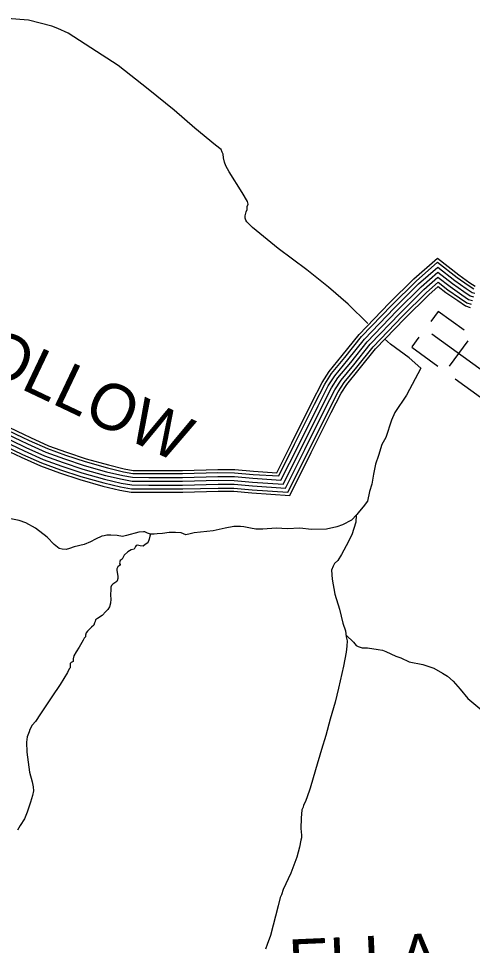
# Model space of a CAD drawing. Extents: x 1551132 to 1791609, y 378168 to 563823.
# Drawn here: x 1665834 to 1669476, y 396855 to 404298 of the extents above; entities that cross this region are included whole.
import ezdxf

# ---------------------------------------------------------------- set-up
doc = ezdxf.new("R2010")
doc.units = 0
for name, color, linetype in [('DESIGN - ROW - Right-of-Way and Easement Labels', 7, 'Continuous'), ('DESIGN - TRANSPORTATION - Text', 7, 'Continuous'), ('DESIGN - UTILITIES - Cable (Underground) with Text', 7, 'Continuous'), ('SURVEY - PROPERTY - Owners', 7, 'Continuous'), ('SURVEY - TRANSPORTATION - Roads', 7, 'Continuous')]:
    doc.layers.add(name, color=color, linetype=linetype)

msp = doc.modelspace()

# ---------------------------------------------------------------- linework, layer by layer
at = {"layer": 'DESIGN - TRANSPORTATION - Text'}
for points in [[(1668636.694, 401848.028), (1668479.889, 402002.974), (1668320.46, 402141.836), (1668147.03, 402278.747), (1667917.744, 402449.943), (1667712.441, 402619.031), (1667678.575, 402651.215), (1667666.633, 402665.282), (1667658.684, 402679.333), (1667652.75, 402695.383), (1667652.817, 402713.4), (1667660.942, 402745.401), (1667669.008, 402763.385), (1667669.1, 402787.411), (1667677.175, 402807.403), (1667671.267, 402829.453), (1667627.543, 402899.722), (1667524.212, 403066.368), (1667498.404, 403114.527), (1667486.53, 403144.62), (1667478.663, 403178.687), (1667474.78, 403208.738), (1667468.838, 403224.789), (1667458.922, 403244.856), (1667415.073, 403281.082), (1667249.635, 403417.96), (1667082.239, 403562.864), (1666874.927, 403729.96), (1666633.717, 403919.223), (1666414.322, 404062.344), (1666232.809, 404179.272), (1666148.978, 404217.681), (1666101.063, 404235.915), (1665915.292, 404284.782), (1665743.379, 404297.549)], [(1669061.125, 401490.285), (1668968.111, 401572.354), (1668818.573, 401683.132), (1668770.99, 401725.491)], [(1669061.125, 401490.285), (1668945.828, 401274.738), (1668853.305, 401134.984), (1668825.072, 401073.033), (1668780.54, 400933.071), (1668748.332, 400877.152), (1668721.999, 400789.167), (1668697.733, 400719.19), (1668681.425, 400639.171), (1668667.117, 400559.144), (1668650.893, 400499.142), (1668632.601, 400423.14), (1668598.427, 400377.239), (1668570.294, 400341.322), (1668548.203, 400315.388), (1668504.038, 400269.528), (1668431.906, 400231.802), (1668387.857, 400215.976), (1668305.801, 400198.309), (1668183.82, 400194.842), (1668089.881, 400205.268), (1667991.883, 400199.684), (1667901.927, 400206.084), (1667793.921, 400198.551), (1667737.922, 400196.792), (1667693.965, 400204.993), (1667642.016, 400215.234), (1667614.042, 400219.36), (1667588.051, 400219.476), (1667562.051, 400219.584), (1667492.02, 400205.876), (1667395.955, 400184.275), (1667243.925, 400168.925), (1667209.901, 400159.058), (1667175.885, 400153.199), (1667157.919, 400161.291), (1667139.944, 400167.375), (1667093.971, 400171.583), (1667041.98, 400169.808), (1666987.956, 400162.033), (1666945.966, 400160.216), (1666921.958, 400158.316), (1666907.967, 400158.383), (1666891.967, 400158.449), (1666870.001, 400166.558), (1666846.051, 400176.666), (1666836.052, 400176.716), (1666800.044, 400172.866), (1666699.963, 400147.274), (1666667.947, 400139.407), (1666625.981, 400147.599), (1666574.008, 400149.832), (1666542.017, 400149.965), (1666519.992, 400144.057), (1666501.984, 400140.132), (1666451.911, 400118.323), (1666411.836, 400096.481), (1666361.763, 400074.672), (1666281.706, 400054.996), (1666243.657, 400041.146), (1666215.641, 400035.262), (1666183.658, 400037.404), (1666159.684, 400043.521), (1666119.81, 400073.73), (1666064.061, 400134.04), (1665970.355, 400204.533), (1665892.54, 400248.918), (1665838.625, 400267.177), (1665772.685, 400279.477)], [(1668542.562, 400309.529), (1668539.095, 400252.728), (1668506.712, 400150.758), (1668462.38, 400062.847), (1668424.123, 399992.937), (1668395.948, 399947.011), (1668369.857, 399921.094), (1668357.783, 399901.127), (1668345.658, 399869.142), (1668349.374, 399797.04), (1668372.899, 399674.804), (1668408.423, 399554.509), (1668435.989, 399442.256), (1668457.747, 399382.096), (1668463.563, 399334.02), (1668469.43, 399299.952), (1668467.263, 399257.91), (1668463.08, 399209.875), (1668440.655, 399097.847), (1668399.973, 398919.826), (1668373.548, 398807.814), (1668333.024, 398671.836), (1668298.525, 398539.832), (1668264.101, 398427.863), (1668215.477, 398263.883), (1668172.919, 398117.904), (1668146.62, 398039.936), (1668134.495, 398005.943), (1668120.404, 397981.984), (1668118.345, 397965.967), (1668106.262, 397944), (1668102.004, 397877.94), (1668097.679, 397793.862), (1668103.479, 397741.778), (1668103.396, 397719.761), (1668099.321, 397699.752), (1668087.104, 397643.742), (1668066.796, 397563.74), (1668018.314, 397435.803), (1667957.816, 397303.924), (1667943.658, 397261.932), (1667933.574, 397239.956), (1667917.316, 397171.946), (1667856.409, 396933.94), (1667828.135, 396861.988), (1667815.994, 396823.995)], [(1666892.825, 400158.449), (1666887.042, 400141.824), (1666882.95, 400117.815), (1666870.834, 400087.839), (1666850.785, 400073.905), (1666832.743, 400061.972), (1666808.76, 400064.08), (1666788.786, 400070.172), (1666778.77, 400066.213), (1666772.745, 400058.23), (1666760.67, 400038.263), (1666736.645, 400030.354), (1666710.588, 400014.454), (1666680.497, 399988.553), (1666664.372, 399956.585), (1666648.339, 399946.652), (1666644.264, 399926.643), (1666650.447, 399914.843), (1666644.181, 399906.617), (1666630.14, 399894.667), (1666624.081, 399878.675), (1666622.031, 399864.666), (1666629.856, 399820.582), (1666629.79, 399802.565), (1666626.106, 399783.364), (1666621.69, 399776.572), (1666589.607, 399754.688), (1666579.574, 399744.721), (1666575.516, 399730.721), (1666573.457, 399714.712), (1666571.274, 399666.669), (1666575.149, 399634.61), (1666573.032, 399604.593), (1666564.916, 399574.592), (1666550.833, 399552.625), (1666534.775, 399536.683), (1666504.659, 399504.773), (1666466.577, 399480.914), (1666452.535, 399468.964), (1666448.485, 399456.964), (1666444.444, 399444.972), (1666438.377, 399426.98), (1666418.319, 399411.046), (1666400.253, 399393.104), (1666386.203, 399379.153), (1666376.154, 399365.178), (1666372.079, 399347.178), (1666372.029, 399333.161), (1666361.979, 399321.194), (1666353.921, 399305.21), (1666321.721, 399251.283), (1666297.572, 399211.349), (1666277.456, 399179.398), (1666273.373, 399157.389), (1666271.323, 399145.389), (1666271.281, 399135.372), (1666257.256, 399127.43), (1666249.231, 399119.455), (1666249.165, 399103.438), (1666247.131, 399095.438), (1666249.09, 399083.412), (1666241.057, 399075.437), (1666226.957, 399047.47), (1666168.6, 398951.617), (1666100.226, 398851.798), (1666011.72, 398716.036), (1665971.488, 398654.142), (1665943.38, 398624.225), (1665925.255, 398590.266), (1665919.172, 398570.273), (1665903.023, 398530.297), (1665896.864, 398488.28), (1665900.556, 398408.169), (1665921.922, 398245.89), (1665943.621, 398169.713), (1665951.455, 398127.628), (1665953.329, 398095.586), (1665945.196, 398059.577), (1665928.988, 398005.584), (1665904.689, 397925.606), (1665882.481, 397871.638), (1665848.282, 397817.729), (1665826.149, 397781.786)], [(1668461.98, 399347.087), (1668521.378, 399289.71), (1668543.27, 399263.585), (1668559.236, 399255.51), (1668591.185, 399245.359), (1668633.176, 399245.176), (1668719.107, 399230.784), (1668753.081, 399226.626), (1668781.031, 399216.492), (1668860.87, 399178.099), (1668900.803, 399163.916), (1668968.668, 399133.582), (1669078.557, 399111.073), (1669166.43, 399082.655), (1669236.262, 399042.304), (1669274.152, 399016.112), (1669321.984, 398975.853), (1669377.716, 398911.543), (1669439.415, 398837.182), (1669551.037, 398744.597)]]:
    msp.add_lwpolyline(points, dxfattribs=at)
at = {"layer": 'DESIGN - UTILITIES - Cable (Underground) with Text'}
for p, q in [((1669200.74, 401945.692), (1669142.092, 401864.993)), ((1669408.379, 401794.773), (1669200.656, 401945.601)), ((1669046.57, 401740.345), (1668988.497, 401660.263)), ((1669439.304, 401710.517), (1669289.934, 401505.436)), ((1668988.097, 401659.738), (1669199.028, 401506.493)), ((1669337.41, 401405.913), (1669540.907, 401258.21))]:
    msp.add_line(p, q, dxfattribs=at)
msp.add_lwpolyline([(1669148.868, 401766.395), (1669604.304, 401435.657)], dxfattribs=at)
at = {"layer": 'SURVEY - PROPERTY - Owners'}
msp.add_lwpolyline([(1665665.421, 400962.003), (1665892.599, 400854.134), (1666042.095, 400786.907), (1666191.684, 400733.689), (1666351.272, 400680.404), (1666532.867, 400628.953), (1666664.614, 400597.902), (1666746.496, 400583.26), (1666878.459, 400582.252), (1667150.403, 400582.169), (1667434.396, 400590.011), (1667564.36, 400589.011), (1667712.231, 400575.869), (1667958.067, 400559.969), (1668104.106, 400851.218), (1668264.36, 401174.402), (1668345.467, 401331.973), (1668396.016, 401411.691), (1668498.888, 401537.061), (1668632.035, 401702.249), (1668869.747, 401950.747), (1669065.067, 402143.494), (1669197.872, 402260.631), (1669315.203, 402169.62), (1669406.726, 402104.835), (1669458.466, 402070.393), (1669484.774, 402061.867)], dxfattribs=at)
at = {"layer": 'SURVEY - TRANSPORTATION - Roads'}
for points in [[(1665704.762, 401039.322), (1665928.982, 400932.852), (1666074.461, 400867.434), (1666219.95, 400815.675), (1666376.838, 400763.29), (1666554.642, 400712.914), (1666682.205, 400682.855), (1666754.512, 400669.921), (1666878.801, 400668.971), (1667149.22, 400668.888), (1667433.53, 400676.738), (1667568.535, 400675.697), (1667718.865, 400662.338), (1667906.31, 400650.213), (1668026.507, 400889.919), (1668186.962, 401213.511), (1668270.152, 401375.124), (1668325.617, 401462.609), (1668431.615, 401591.779), (1668566.829, 401759.534), (1668807.948, 402011.599), (1669005.885, 402206.929), (1669194.323, 402373.134), (1669366.852, 402239.305), (1669455.808, 402176.337), (1669496.565, 402149.203)], [(1665679.487, 400989.645), (1665905.607, 400882.276), (1666053.662, 400815.691), (1666201.792, 400762.998), (1666360.413, 400710.038), (1666540.65, 400658.971), (1666670.906, 400628.27), (1666749.362, 400614.236), (1666878.584, 400613.253), (1667149.978, 400613.17), (1667434.088, 400621.012), (1667565.851, 400620.003), (1667714.606, 400606.778), (1667939.568, 400592.228), (1668076.365, 400865.052), (1668236.694, 401188.385), (1668318.543, 401347.398), (1668370.85, 401429.892), (1668474.839, 401556.62), (1668608.728, 401722.725), (1668847.655, 401972.498), (1669043.909, 402166.17), (1669196.606, 402300.849), (1669333.669, 402194.529), (1669424.275, 402130.394), (1669472.083, 402098.568), (1669494.332, 402091.36)], [(1665693.545, 401017.28), (1665918.607, 400910.419), (1666065.237, 400844.484), (1666211.891, 400792.307), (1666369.546, 400739.664), (1666548.434, 400688.988), (1666677.189, 400658.637), (1666752.229, 400645.22), (1666878.709, 400644.254), (1667149.553, 400644.17), (1667433.78, 400652.021), (1667567.351, 400650.988), (1667716.973, 400637.696), (1667921.068, 400624.495), (1668048.624, 400878.885), (1668209.02, 401202.361), (1668291.618, 401362.823), (1668345.684, 401448.092), (1668450.79, 401576.179), (1668585.42, 401743.209), (1668825.564, 401994.249), (1669022.76, 402188.845), (1669195.339, 402341.066), (1669352.127, 402219.446), (1669441.817, 402155.953), (1669485.707, 402126.744)], [(1665651.355, 400934.361), (1665879.591, 400825.991), (1666030.529, 400758.123), (1666181.575, 400704.38), (1666342.13, 400650.77), (1666525.084, 400598.936), (1666658.323, 400567.535), (1666743.629, 400552.285), (1666878.334, 400551.251), (1667150.828, 400551.168), (1667434.704, 400559.01), (1667562.868, 400558.018), (1667709.856, 400544.96), (1667976.567, 400527.71), (1668131.847, 400837.384), (1668292.026, 401160.418), (1668372.391, 401316.547), (1668421.182, 401393.491), (1668522.938, 401517.503), (1668655.343, 401681.774), (1668891.838, 401928.997), (1669086.225, 402120.819), (1669199.139, 402220.413), (1669296.737, 402144.711), (1669389.176, 402079.276), (1669444.85, 402042.217), (1669475.216, 402032.375)], [(1665665.421, 400962.003), (1665892.599, 400854.134), (1666042.095, 400786.907), (1666191.684, 400733.689), (1666351.272, 400680.404), (1666532.867, 400628.953), (1666664.614, 400597.902), (1666746.496, 400583.26), (1666878.459, 400582.252), (1667150.403, 400582.169), (1667434.396, 400590.011), (1667564.36, 400589.011), (1667712.231, 400575.869), (1667958.067, 400559.969), (1668104.106, 400851.218), (1668264.36, 401174.402), (1668345.467, 401331.973), (1668396.016, 401411.691), (1668498.888, 401537.061), (1668632.035, 401702.249), (1668869.747, 401950.747), (1669065.067, 402143.494), (1669197.872, 402260.631), (1669315.203, 402169.62), (1669406.726, 402104.835), (1669458.466, 402070.393), (1669484.774, 402061.867)], [(1665665.421, 400962.003), (1665892.599, 400854.134), (1666042.095, 400786.907), (1666191.684, 400733.689), (1666351.272, 400680.404), (1666532.867, 400628.953), (1666664.614, 400597.902), (1666746.496, 400583.26), (1666878.459, 400582.252), (1667150.403, 400582.169), (1667434.396, 400590.011), (1667564.36, 400589.011), (1667712.231, 400575.869), (1667958.067, 400559.969), (1668104.106, 400851.218), (1668264.36, 401174.402), (1668345.467, 401331.973), (1668396.016, 401411.691), (1668498.888, 401537.061), (1668632.035, 401702.249), (1668869.747, 401950.747), (1669065.067, 402143.494), (1669197.872, 402260.631), (1669315.203, 402169.62), (1669406.726, 402104.835), (1669458.466, 402070.393), (1669484.774, 402061.867)], [(1665625.63, 400883.793), (1665855.8, 400774.507), (1666009.355, 400705.447), (1666163.093, 400650.753), (1666325.414, 400596.56), (1666510.843, 400544.026), (1666646.823, 400511.975), (1666738.379, 400495.6), (1666878.109, 400494.533), (1667151.603, 400494.45), (1667435.271, 400502.284), (1667560.135, 400501.325), (1667705.515, 400488.4), (1668010.416, 400468.683), (1668182.604, 400812.075), (1668342.65, 401134.842), (1668421.657, 401288.321), (1668467.222, 401360.19), (1668566.937, 401481.71), (1668697.992, 401644.298), (1668932.253, 401889.196), (1669124.932, 402079.334), (1669201.464, 402146.836), (1669262.962, 402099.135), (1669357.077, 402032.508), (1669419.925, 401990.674), (1669457.733, 401978.424)], [(1665637.297, 400906.727), (1665866.591, 400797.849), (1666018.954, 400729.33), (1666171.476, 400675.071), (1666332.997, 400621.144), (1666517.301, 400568.918), (1666652.039, 400537.167), (1666740.762, 400521.3), (1666878.209, 400520.25), (1667151.253, 400520.167), (1667435.013, 400528.001), (1667561.368, 400527.034), (1667707.49, 400514.042), (1667995.066, 400495.442), (1668159.588, 400823.551), (1668319.701, 401146.443), (1668399.316, 401301.122), (1668446.348, 401375.29), (1668546.987, 401497.944), (1668678.651, 401661.29), (1668913.929, 401907.246), (1669107.374, 402098.143), (1669200.406, 402180.195), (1669278.279, 402119.794), (1669371.635, 402053.717), (1669431.225, 402014.041), (1669465.666, 402002.882)]]:
    msp.add_lwpolyline(points, dxfattribs=at)

# ---------------------------------------------------------------- texts
at = {"layer": 'DESIGN - ROW - Right-of-Way and Easement Labels'}
for s, height, rotation, p in [('HOLLOW', 369.9946, 334.6002806, (1665171.908, 401647.679)), ('ELLA', 369.9914, 2.57865, (1668009.089, 396531.987))]:
    msp.add_text(s, height=height, rotation=rotation, dxfattribs=at).set_placement(p)

doc.saveas('drawing.dxf')
